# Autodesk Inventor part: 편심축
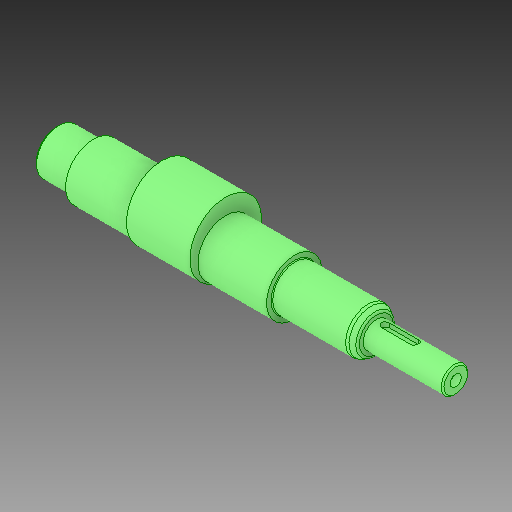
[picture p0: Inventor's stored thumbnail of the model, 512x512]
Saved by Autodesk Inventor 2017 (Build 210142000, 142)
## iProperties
Created: 2024-09
Part Number: 편심축
Material: 일반
Document SubType Name: Modeling
Designer: MRC
Density: 1 g/cm^3
Appearance: 기본값
Author: jhkim
Sending System: Autodesk Inventor 2025
Preprocessor: ST-DEVELOPER v20
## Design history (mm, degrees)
feature "솔리드1"
node "솔리드2"
